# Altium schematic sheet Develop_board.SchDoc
size A; SheetNumber: 1; SheetTotal: 1
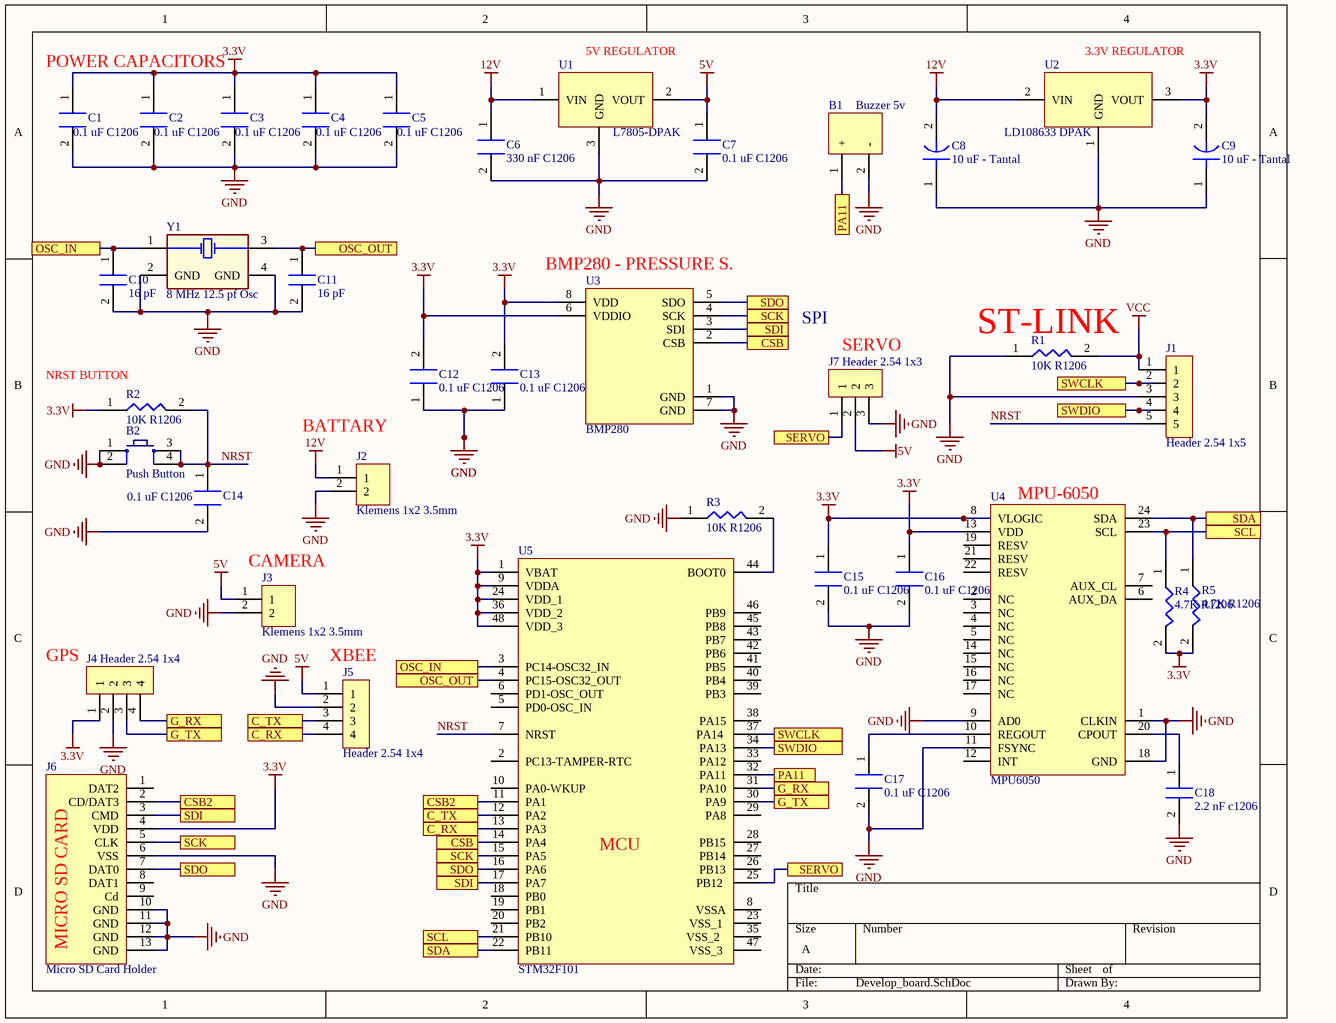
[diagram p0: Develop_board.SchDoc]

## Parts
B1  Buzzer 5v  [Buzzer 5v]
B2  Push Button  [PUSB BUTTON-SMD]
C1  0.1 uF C1206  [C1206]
C2  0.1 uF C1206  [C1206]
C3  0.1 uF C1206  [C1206]
C4  0.1 uF C1206  [C1206]
C5  0.1 uF C1206  [C1206]
C6  330 nF C1206  [C1206]
C7  0.1 uF C1206  [C1206]
C8  10 uF - Tantal  [C1206- TANTAL]
C9  10 uF - Tantal  [C1206- TANTAL]
C10  16 pF  [C1206]
C11  16 pF  [C1206]
C12  0.1 uF C1206  [C1206]
C13  0.1 uF C1206  [C1206]
C14  0.1 uF C1206  [C1206]
C15  0.1 uF C1206  [C1206]
C16  0.1 uF C1206  [C1206]
C17  0.1 uF C1206  [C1206]
C18  2.2 nF c1206  [C1206]
J1  Header 2.54 1x5  [Header 2.54 1x5]
J2  Klemens 1x2 3.5mm  [Klemens 1x2 - 3.5mm]
J3  Klemens 1x2 3.5mm  [Klemens 1x2 - 3.5mm]
J4  Header 2.54 1x4  [Header 2.54 1x4]
J5  Header 2.54 1x4  [Header 2.54 1x4]
J6  Micro SD Card Holder  [Micro SD Card Holder]
J7  Header 2.54 1x3  [Header 2.54 1x3]
R1  10K R1206  [R1206 Resistor]
R2  10K R1206  [R1206 Resistor]
R3  10K R1206  [R1206 Resistor]
R4  4.7K R1206  [R1206 Resistor]
R5  4.7K R1206  [R1206 Resistor]
U1  L7805-DPAK  [DPAK228P972X230-3N]
U2  LD108633 DPAK  [DPAK228P972X230-3N]
U3  BMP280  [BMP280]
U4  MPU6050  [QFN50P400X400X90_HS-25N]
U5  STM32F101  [LQFP48-STM]
Y1  8 MHz 12.5 pf Osc  [8 MHZ Osc.]

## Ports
C_RX, C_TX, CSB, CSB2, G_RX, G_TX, OSC_IN, OSC_OUT, PA11, SCK, SCL, SDA, SDI, SDO, SERVO, SWCLK, SWDIO

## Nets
3.3V: C1.1 C2.1 C3.1 C4.1 C5.1 C9.2 C12.2 C13.2 C15.1 C16.1 J4.1 J6.4(VDD) R2.1 R4.2 R5.2 U2.3(VOUT) U3.6(VDDIO) U3.8(VDD) U4.8(VLOGIC) U4.13(VDD) U5.1(VBAT) U5.9(VDDA) U5.24(VDD_1) U5.36(VDD_2) U5.48(VDD_3)
5V: C7.1 J3.1 J5.1 J7.2 U1.2(VOUT)
12V: C6.1 C8.2 J2.1 U1.1(VIN) U2.2(VIN)
GND: B1.2(-) B2.1 B2.2 C1.2 C2.2 C3.2 C4.2 C5.2 C6.2 C7.2 C8.1 C9.1 C10.2 C11.2 C12.1 C13.1 C14.2 C15.2 C16.2 C17.2 C18.2 J1.3 J2.2 J3.2 J4.2 J5.2 J6.6(VSS) J6.10(GND) J6.11(GND) J6.12(GND) J6.13(GND) J7.3 R1.1 R3.1 U1.3(GND) U2.1(GND) U3.1(GND) U3.7(GND) U4.1(CLKIN) U4.9(AD0) U4.11(FSYNC) U4.18(GND) Y1.2(GND) Y1.4(GND)
VCC: J1.1 R1.2
C_RX: J5.4 U5.13(PA3) ; port C_RX
C_TX: J5.3 U5.12(PA2) ; port C_TX
CSB: U3.2(CSB) U5.14(PA4) ; port CSB
CSB2: J6.2(CD/DAT3) U5.11(PA1) ; port CSB2
G_RX: J4.4 U5.31(PA10) ; port G_RX
G_TX: J4.3 U5.30(PA9) ; port G_TX
NRST: B2.3 B2.4 C14.1 J1.5 R2.2 U5.7(NRST)
OSC_IN: C10.1 U5.3(PC14-OSC32_IN) Y1.1 ; port OSC_IN
OSC_OUT: C11.1 U5.4(PC15-OSC32_OUT) Y1.3 ; port OSC_OUT
PA11: B1.1(+) U5.32(PA11) ; port PA11
SCK: J6.5(CLK) U3.4(SCK) U5.15(PA5) ; port SCK
SCL: R4.1 U4.23(SCL) U5.21(PB10) ; port SCL
SDA: R5.1 U4.24(SDA) U5.22(PB11) ; port SDA
SDI: J6.3(CMD) U3.3(SDI) U5.17(PA7) ; port SDI
SDO: J6.7(DAT0) U3.5(SDO) U5.16(PA6) ; port SDO
SERVO: J7.1 U5.25(PB12) ; port SERVO
SWCLK: J1.2 U5.37(PA14) ; port SWCLK
SWDIO: J1.4 U5.34(PA13) ; port SWDIO
NetC17_1: C17.1 U4.10(REGOUT)
NetC18_1: C18.1 U4.20(CPOUT)
NetR3_2: R3.2 U5.44(BOOT0)

Not connected (* = marked no-connect by the designer): J6 1(DAT2) 8(DAT1) 9(Cd); U4 2(NC) 3(NC) 4(NC) 5(NC) 6(AUX_DA) 7(AUX_CL) 12(INT) 14(NC) 15(NC) 16(NC) 17(NC) 19(RESV) 21(RESV) 22(RESV); U5 2(PC13-TAMPER-RTC) 5(PD0-OSC_IN) 6(PD1-OSC_OUT) 8(VSSA) 10(PA0-WKUP) 18(PB0) 19(PB1) 20(PB2) 23(VSS_1_) 26(PB13) 27(PB14) 28(PB15) 29(PA8) 33(PA12) 35(VSS_2__) 38(PA15) 39(PB3) 40(PB4) 41(PB5) 42(PB6) 43(PB7) 45(PB8) 46(PB9) 47(VSS_3_)

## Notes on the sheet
- POWER CAPACITORS
- (near U1) 5V REGULATOR
- (near U2) 3.3V REGULATOR
- (near U3) BMP280 - PRESSURE S.
- SPI
- (near J7) SERVO
- (near R1) ST-LINK
- (near R2) NRST BUTTON
- (near J2) BATTARY
- (near U4) MPU-6050
- (near J3) CAMERA
- (near J4) GPS
- (near J5) XBEE
- (near U5) MCU
- MICRO SD CARD

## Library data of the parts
B2 = Push Button: Smd Push Button
R1 = 4.7K R1206
U1 = L7805-DPAK: L7805 5V REGULATOR. SMD PAKET
U2 = LD108633 DPAK: LD1086 3.3V REGULATOR
U3 = BMP280: BMP280 SENSOR
U4 = MPU6050: MPU6050 GYRO SENSOR
U5 = STM32F101: STM32F101 48 PİNLİ MİKROİŞLEMCİ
